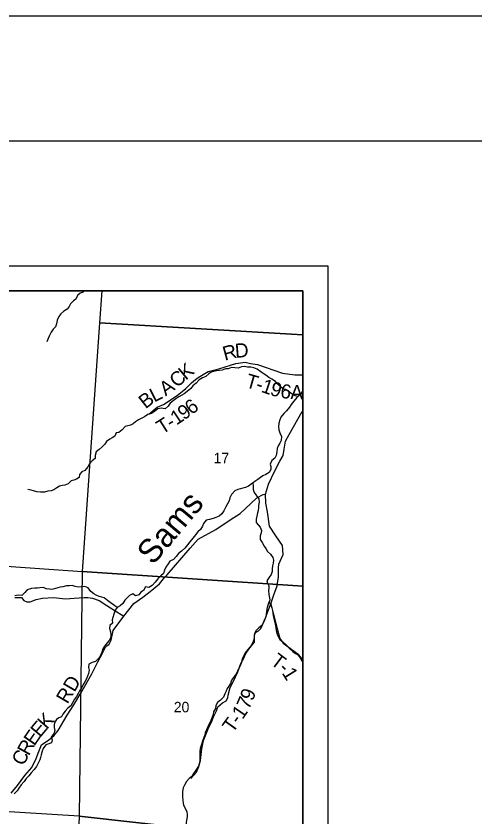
# Model space of a CAD drawing. Extents: x -13.1 to 43.1, y 0 to 22.
# Drawn here: x 7.753 to 9.588, y 18.795 to 22 of the extents above; entities that cross this region are included whole.
import ezdxf

# ---------------------------------------------------------------- set-up
doc = ezdxf.new("R2010")
doc.units = 0
for name, color, linetype in [('GM_X_Corporation', 7, 'Continuous'), ('GM_X_Minor_River', 7, 'Continuous'), ('GM_X_Minor_River_Text', 7, 'Continuous'), ('GM_X_Section_Text', 7, 'Continuous'), ('GM_X_Township_Road', 7, 'Continuous'), ('GM_X_Township_Road_Text', 7, 'Continuous'), ('SH_Border', 7, 'Continuous'), ('SH_Data', 7, 'Continuous')]:
    doc.layers.add(name, color=color, linetype=linetype)

msp = doc.modelspace()

# ---------------------------------------------------------------- linework, layer by layer
at = {"layer": 'GM_X_Corporation'}
for points in [[(8.9, 15.7487), (8.9, 20.9), (7.0804, 20.9), (7.0615, 20.6138), (7.0162, 19.896), (7.0106, 19.8452), (6.9616, 19.1692), (6.9507, 19.0184), (6.8365, 17.1257), (6.8234, 16.908), (6.7528, 15.9566), (7.8612, 15.855), (8.7782, 15.7572)], [(8.9, 15.7487), (8.9, 20.9), (7.0804, 20.9), (7.0615, 20.6138), (7.0162, 19.896), (7.0106, 19.8452), (6.9616, 19.1692), (6.9507, 19.0184), (6.8365, 17.1257), (6.8234, 16.908), (6.7528, 15.9566), (7.8612, 15.855), (8.7782, 15.7572)], [(8.9, 15.7481), (8.9, 20.9), (7.0807, 20.9), (7.0617, 20.6133), (7.0164, 19.8954), (7.0108, 19.8446), (6.9509, 19.0179), (6.8236, 16.9075), (6.7531, 15.956), (7.8614, 15.8545), (8.7784, 15.7567)], [(8.9, 20.7241), (8.9, 20.9), (8.0957, 20.9), (8.0867, 20.7729)], [(8.9, 19.7189), (8.9, 20.7241), (8.0867, 20.7729), (8.018, 19.7768)], [(7.0116, 19.8485), (8.018, 19.7768), (8.0053, 18.7983), (6.947, 18.8637), (6.949, 18.894)], [(8.9, 18.698), (8.9, 19.7189), (8.018, 19.7768), (8.0053, 18.7983)], [(8.9, 17.7183), (8.9, 18.698), (8.0053, 18.7983), (7.9639, 17.8036)]]:
    msp.add_lwpolyline(points, close=True, dxfattribs=at)
at = {"layer": 'GM_X_Minor_River'}
for p, q in [((8.0214, 20.8952), (8.01, 20.8907)), ((8.024, 20.9), (8.0214, 20.8952)), ((7.9921, 20.8674), (7.9825, 20.8598)), ((7.9986, 20.8813), (7.9921, 20.8674)), ((8.01, 20.8907), (7.9986, 20.8813)), ((7.9653, 20.8372), (7.9573, 20.8274)), ((7.9715, 20.8485), (7.9653, 20.8372)), ((7.9825, 20.8598), (7.9715, 20.8485)), ((7.9322, 20.8082), (7.9245, 20.7984)), ((7.9448, 20.8191), (7.9322, 20.8082)), ((7.9573, 20.8274), (7.9448, 20.8191)), ((7.9152, 20.7685), (7.9114, 20.7567)), ((7.9172, 20.7836), (7.9152, 20.7685)), ((7.9245, 20.7984), (7.9172, 20.7836)), ((7.893, 20.7349), (7.8853, 20.7197)), ((7.9022, 20.7466), (7.893, 20.7349)), ((7.9114, 20.7567), (7.9022, 20.7466)), ((7.8811, 20.7099), (7.8757, 20.6967)), ((7.8853, 20.7197), (7.8811, 20.7099)), ((8.5334, 20.5752), (8.5239, 20.5688)), ((8.5444, 20.5782), (8.5334, 20.5752)), ((8.5554, 20.5804), (8.5444, 20.5782)), ((8.5664, 20.5811), (8.5554, 20.5804)), ((8.5774, 20.5833), (8.5664, 20.5811)), ((8.5914, 20.5877), (8.5774, 20.5833)), ((8.602, 20.5881), (8.5914, 20.5877)), ((8.6149, 20.594), (8.602, 20.5881)), ((8.6282, 20.5917), (8.6149, 20.594)), ((8.6414, 20.5905), (8.6282, 20.5917)), ((8.6551, 20.5961), (8.6414, 20.5905)), ((8.6653, 20.5971), (8.6551, 20.5961)), ((8.6786, 20.5955), (8.6653, 20.5971)), ((8.6922, 20.5947), (8.6786, 20.5955)), ((8.7035, 20.5927), (8.6922, 20.5947)), ((8.7168, 20.5869), (8.7035, 20.5927)), ((8.7318, 20.5758), (8.7168, 20.5869)), ((8.742, 20.5697), (8.7318, 20.5758)), ((8.4851, 20.5448), (8.4729, 20.5312)), ((8.4991, 20.5527), (8.4851, 20.5448)), ((8.5121, 20.5579), (8.4991, 20.5527)), ((8.5239, 20.5688), (8.5121, 20.5579)), ((8.7526, 20.5624), (8.742, 20.5697)), ((8.7646, 20.554), (8.7526, 20.5624)), ((8.7763, 20.5467), (8.7646, 20.554)), ((8.7903, 20.5383), (8.7763, 20.5467)), ((8.4607, 20.5199), (8.4519, 20.5098)), ((8.4729, 20.5312), (8.4607, 20.5199)), ((8.8004, 20.5265), (8.7903, 20.5383)), ((8.8102, 20.5158), (8.8004, 20.5265)), ((8.8211, 20.5081), (8.8102, 20.5158)), ((8.4161, 20.4834), (8.4035, 20.4763)), ((8.426, 20.4879), (8.4161, 20.4834)), ((8.4381, 20.4973), (8.426, 20.4879)), ((8.4519, 20.5098), (8.4381, 20.4973)), ((8.8309, 20.505), (8.8211, 20.5081)), ((8.8449, 20.4962), (8.8309, 20.505)), ((8.8588, 20.4851), (8.8449, 20.4962)), ((8.869, 20.4809), (8.8588, 20.4851)), ((8.8809, 20.4772), (8.869, 20.4809)), ((8.3696, 20.4507), (8.3616, 20.4387)), ((8.3811, 20.4605), (8.3696, 20.4507)), ((8.3921, 20.468), (8.3811, 20.4605)), ((8.4035, 20.4763), (8.3921, 20.468)), ((8.3069, 20.4178), (8.2951, 20.4095)), ((8.3199, 20.4279), (8.3069, 20.4178)), ((8.3331, 20.4305), (8.3199, 20.4279)), ((8.3494, 20.4289), (8.3331, 20.4305)), ((8.3616, 20.4387), (8.3494, 20.4289)), ((8.2423, 20.3848), (8.2313, 20.3758)), ((8.256, 20.3908), (8.2423, 20.3848)), ((8.2663, 20.3968), (8.256, 20.3908)), ((8.2799, 20.405), (8.2663, 20.3968)), ((8.2951, 20.4095), (8.2799, 20.405)), ((8.1898, 20.3575), (8.1776, 20.3443)), ((8.2001, 20.3604), (8.1898, 20.3575)), ((8.2103, 20.3623), (8.2001, 20.3604)), ((8.221, 20.3683), (8.2103, 20.3623)), ((8.2313, 20.3758), (8.221, 20.3683)), ((8.1487, 20.3194), (8.1376, 20.3123)), ((8.1537, 20.3319), (8.1487, 20.3194)), ((8.1647, 20.3341), (8.1537, 20.3319)), ((8.1776, 20.3443), (8.1647, 20.3341)), ((8.1079, 20.2867), (8.0976, 20.2758)), ((8.1152, 20.2976), (8.1079, 20.2867)), ((8.1281, 20.3074), (8.1152, 20.2976)), ((8.1376, 20.3123), (8.1281, 20.3074)), ((8.074, 20.2566), (8.0701, 20.2422)), ((8.0858, 20.2656), (8.074, 20.2566)), ((8.0976, 20.2758), (8.0858, 20.2656)), ((8.0693, 20.2297), (8.0582, 20.2199)), ((8.0701, 20.2422), (8.0693, 20.2297)), ((8.0398, 20.1957), (8.0276, 20.1814)), ((8.0468, 20.2086), (8.0398, 20.1957)), ((8.0582, 20.2199), (8.0468, 20.2086)), ((8.0063, 20.1652), (8.0051, 20.1538)), ((8.0166, 20.1758), (8.0063, 20.1652)), ((8.0276, 20.1814), (8.0166, 20.1758)), ((7.961, 20.1283), (7.9481, 20.1235)), ((7.9736, 20.1404), (7.961, 20.1283)), ((7.9842, 20.143), (7.9736, 20.1404)), ((7.9948, 20.1463), (7.9842, 20.143)), ((8.0051, 20.1538), (7.9948, 20.1463)), ((7.8131, 20.1031), (7.8006, 20.1059)), ((7.8233, 20.1008), (7.8131, 20.1031)), ((7.8369, 20.0961), (7.8233, 20.1008)), ((7.8513, 20.0953), (7.8369, 20.0961)), ((7.8668, 20.0952), (7.8513, 20.0953)), ((7.8801, 20.0985), (7.8668, 20.0952)), ((7.8934, 20.1007), (7.8801, 20.0985)), ((7.9036, 20.1041), (7.8934, 20.1007)), ((7.9158, 20.1123), (7.9036, 20.1041)), ((7.9264, 20.1183), (7.9158, 20.1123)), ((7.9382, 20.1217), (7.9264, 20.1183)), ((7.9481, 20.1235), (7.9382, 20.1217)), ((7.8288, 19.7101), (7.8148, 19.709)), ((7.839, 19.7112), (7.8288, 19.7101)), ((7.8489, 19.7126), (7.839, 19.7112)), ((7.8625, 19.7137), (7.8489, 19.7126)), ((7.8735, 19.7087), (7.8625, 19.7137)), ((7.9197, 19.7125), (7.9068, 19.7077)), ((7.93, 19.7151), (7.9197, 19.7125)), ((7.9398, 19.7166), (7.93, 19.7151)), ((7.955, 19.7195), (7.9398, 19.7166)), ((7.9667, 19.7206), (7.955, 19.7195)), ((7.9773, 19.7213), (7.9667, 19.7206)), ((7.9902, 19.7174), (7.9773, 19.7213)), ((8.0015, 19.715), (7.9902, 19.7174)), ((8.0152, 19.7161), (8.0015, 19.715)), ((8.0288, 19.7179), (8.0152, 19.7161)), ((8.0409, 19.7117), (8.0288, 19.7179)), ((8.0518, 19.6976), (8.0409, 19.7117)), ((7.7612, 19.6825), (7.7487, 19.6799)), ((7.7763, 19.6816), (7.7612, 19.6825)), ((7.7882, 19.6933), (7.7763, 19.6816)), ((7.7981, 19.7038), (7.7882, 19.6933)), ((7.8148, 19.709), (7.7981, 19.7038)), ((7.8863, 19.7067), (7.8735, 19.7087)), ((7.8966, 19.7051), (7.8863, 19.7067)), ((7.9068, 19.7077), (7.8966, 19.7051)), ((8.0638, 19.6877), (8.0518, 19.6976)), ((8.074, 19.6827), (8.0638, 19.6877)), ((8.0861, 19.6769), (8.074, 19.6827)), ((8.0959, 19.6746), (8.0861, 19.6769)), ((8.1057, 19.6719), (8.0959, 19.6746)), ((8.1193, 19.6608), (8.1057, 19.6719)), ((8.1291, 19.6531), (8.1193, 19.6608)), ((8.143, 19.6443), (8.1291, 19.6531)), ((8.7642, 19.6544), (8.7717, 19.6437)), ((8.157, 19.634), (8.143, 19.6443)), ((8.7717, 19.6437), (8.7757, 19.6319)), ((8.7757, 19.6319), (8.7783, 19.6216)), ((8.7783, 19.6216), (8.7801, 19.611)), ((8.7801, 19.611), (8.7819, 19.6)), ((8.7819, 19.6), (8.7845, 19.589)), ((8.7845, 19.589), (8.7871, 19.5772)), ((8.7871, 19.5772), (8.7893, 19.5673)), ((8.7893, 19.5673), (8.7918, 19.554)), ((8.7918, 19.554), (8.7936, 19.5415)), ((8.7936, 19.5415), (8.7973, 19.5271)), ((8.7973, 19.5271), (8.8018, 19.5175)), ((8.8018, 19.5175), (8.8081, 19.505)), ((8.8081, 19.505), (8.8217, 19.4947)), ((8.8217, 19.4947), (8.8345, 19.4832)), ((8.8345, 19.4832), (8.8465, 19.4698)), ((8.8465, 19.4698), (8.8597, 19.458)), ((8.8597, 19.458), (8.8702, 19.4496)), ((8.8702, 19.4496), (8.88, 19.4438)), ((8.88, 19.4438), (8.8898, 19.4324)), ((8.8898, 19.4324), (8.8958, 19.4195)), ((8.8958, 19.4195), (8.9, 19.4132))]:
    msp.add_line(p, q, dxfattribs=at)
for points in [[(8.9, 20.5006), (8.8983, 20.4985), (8.8906, 20.4853), (8.8765, 20.4736), (8.8639, 20.4589), (8.854, 20.4453), (8.8471, 20.4348), (8.8341, 20.4204), (8.8234, 20.4091), (8.8119, 20.3944), (8.8081, 20.3842), (8.8042, 20.3709), (8.8026, 20.3562), (8.8036, 20.3448), (8.8085, 20.3318), (8.8144, 20.3174), (8.8132, 20.3022), (8.8082, 20.2909), (8.8013, 20.2807), (8.797, 20.2693), (8.7958, 20.2564), (8.7938, 20.2413), (8.7884, 20.2307), (8.7759, 20.2221), (8.7689, 20.2069), (8.7723, 20.1974), (8.7718, 20.1853), (8.766, 20.1736), (8.7523, 20.1661), (8.7406, 20.1605), (8.7303, 20.1541), (8.7196, 20.1454), (8.7075, 20.1375), (8.6934, 20.1263), (8.6831, 20.1191), (8.6702, 20.1131), (8.6607, 20.1109), (8.6504, 20.1087), (8.6406, 20.1057), (8.6277, 20.0997)], [(8.6997, 20.1313), (8.7009, 20.1198), (8.7012, 20.1061), (8.7056, 20.0932), (8.7124, 20.0836), (8.724, 20.0688), (8.725, 20.0555), (8.7234, 20.0415), (8.7226, 20.0316), (8.7214, 20.0221), (8.719, 20.0119), (8.7159, 19.9987), (8.7132, 19.9869), (8.7131, 19.974), (8.721, 19.9645), (8.7292, 19.9546), (8.7344, 19.942), (8.7332, 19.9318), (8.7297, 19.9197), (8.73, 19.906), (8.7371, 19.8931), (8.7457, 19.879), (8.7517, 19.8695), (8.7584, 19.8581), (8.7701, 19.8462), (8.7802, 19.8336), (8.7832, 19.8222), (8.7808, 19.8113), (8.7789, 19.7999), (8.7776, 19.7885), (8.7768, 19.7768), (8.7737, 19.7654), (8.7641, 19.7518), (8.7557, 19.7397), (8.759, 19.7302), (8.7643, 19.7203), (8.7638, 19.7109), (8.763, 19.701), (8.764, 19.6851), (8.7673, 19.6725), (8.7676, 19.663), (8.7626, 19.6506), (8.7576, 19.6335), (8.7548, 19.6187), (8.7536, 19.6051), (8.752, 19.5949), (8.7458, 19.5824), (8.742, 19.5722), (8.7366, 19.562), (8.7244, 19.5522), (8.7122, 19.5405), (8.7068, 19.5276), (8.7056, 19.5159), (8.704, 19.5038), (8.6994, 19.4909), (8.6909, 19.4777), (8.6806, 19.466), (8.6695, 19.452), (8.6645, 19.4418), (8.6576, 19.4282), (8.6541, 19.4138), (8.6483, 19.3972), (8.6399, 19.3832), (8.636, 19.3726), (8.6264, 19.3586), (8.6153, 19.342), (8.6103, 19.3295), (8.6042, 19.3186), (8.5973, 19.3087), (8.5934, 19.2981), (8.5877, 19.2876), (8.5823, 19.2751), (8.5712, 19.263), (8.559, 19.2532), (8.5525, 19.2415), (8.5509, 19.2294), (8.5429, 19.2165), (8.5416, 19.2059), (8.5374, 19.1946), (8.532, 19.1813), (8.5262, 19.17), (8.5205, 19.1556), (8.5143, 19.1435), (8.5097, 19.1337), (8.5077, 19.1231), (8.5042, 19.1132), (8.4992, 19.0985), (8.4946, 19.0856), (8.4895, 19.0697), (8.4887, 19.0572), (8.4878, 19.0439), (8.4885, 19.0337), (8.4884, 19.0216), (8.4865, 19.0113), (8.483, 18.9985), (8.4726, 18.983), (8.4634, 18.969), (8.4561, 18.9573), (8.4455, 18.9486), (8.4348, 18.9373), (8.4279, 18.9248)], [(8.6277, 20.0997), (8.6151, 20.0862), (8.6081, 20.0718), (8.605, 20.0601), (8.5993, 20.0487), (8.5916, 20.0359), (8.5847, 20.0208), (8.5762, 20.0083), (8.5652, 19.9985), (8.5523, 19.9929), (8.5409, 19.9892), (8.5268, 19.9855), (8.5128, 19.9825), (8.5029, 19.9697), (8.4982, 19.9584), (8.4902, 19.9455), (8.4807, 19.9365), (8.4707, 19.924), (8.4604, 19.9104), (8.4478, 19.8965), (8.439, 19.884), (8.4279, 19.8712), (8.4153, 19.8584), (8.4032, 19.849), (8.3932, 19.8373), (8.3822, 19.8256), (8.3685, 19.8185), (8.3612, 19.8083), (8.3528, 19.7954), (8.3474, 19.783), (8.3428, 19.7701), (8.3328, 19.7595), (8.3199, 19.7486), (8.3099, 19.7347), (8.2981, 19.7211), (8.284, 19.714), (8.2708, 19.7163), (8.2631, 19.702), (8.2521, 19.6944), (8.2441, 19.6843), (8.2311, 19.6798), (8.2202, 19.6878), (8.2073, 19.6818), (8.1981, 19.672), (8.1878, 19.6622), (8.1802, 19.6494), (8.1695, 19.64), (8.157, 19.634), (8.1489, 19.6223), (8.1439, 19.6068), (8.14, 19.5939), (8.1377, 19.5841), (8.1387, 19.5711), (8.1284, 19.5614), (8.1272, 19.55), (8.1313, 19.5355), (8.1319, 19.5257), (8.1326, 19.5135), (8.1261, 19.5018), (8.1169, 19.4916), (8.1066, 19.4784), (8.0986, 19.4656), (8.0958, 19.4546), (8.0908, 19.441), (8.0839, 19.4312), (8.0709, 19.418), (8.058, 19.4131), (8.0447, 19.4071), (8.0435, 19.3927), (8.0461, 19.3832), (8.0426, 19.3696), (8.0383, 19.3586), (8.0329, 19.3458), (8.0279, 19.3356), (8.0222, 19.3257), (8.0157, 19.3133), (8.0069, 19.3004), (8.0015, 19.2898), (7.995, 19.2777), (7.9873, 19.266), (7.9792, 19.2524), (7.9723, 19.24), (7.9609, 19.2309), (7.9495, 19.2181), (7.9407, 19.2064), (7.9345, 19.1966), (7.9239, 19.1917), (7.9144, 19.1853), (7.9086, 19.1751), (7.9055, 19.1653), (7.9062, 19.1532), (7.9088, 19.141), (7.9037, 19.1281), (7.893, 19.1161), (7.8975, 19.1039), (7.8951, 19.0918), (7.8845, 19.0873), (7.872, 19.0836), (7.8616, 19.0689), (7.8578, 19.0586), (7.8531, 19.0439)], [(7.8531, 19.0439), (7.8508, 19.0337), (7.8477, 19.0238), (7.8415, 19.0102), (7.8346, 18.9973), (7.8254, 18.9856), (7.814, 18.9724), (7.8037, 18.9596), (7.7937, 18.9487), (7.785, 18.937), (7.7739, 18.9238), (7.7639, 18.9106), (7.757, 18.9), (7.7456, 18.8875)], [(8.4279, 18.9248), (8.4217, 18.9124), (8.4194, 18.8972), (8.4185, 18.8862), (8.4188, 18.876), (8.4199, 18.8623), (8.4209, 18.8498), (8.4235, 18.8392), (8.4321, 18.8254), (8.4362, 18.8152), (8.4376, 18.8057), (8.4372, 18.7954), (8.4352, 18.7829), (8.434, 18.7716), (8.432, 18.7583)]]:
    msp.add_lwpolyline(points, dxfattribs=at)
at = {"layer": 'GM_X_Township_Road'}
for points in [[(8.471, 20.5455), (8.4815, 20.554), (8.522, 20.5771), (8.564, 20.588), (8.6315, 20.6098), (8.6698, 20.6147), (8.6908, 20.6103)], [(8.6908, 20.6103), (8.7193, 20.6052), (8.8187, 20.571), (8.8677, 20.5637), (8.9, 20.565)], [(8.2842, 20.4074), (8.3178, 20.4354), (8.3432, 20.4451), (8.3977, 20.482), (8.4324, 20.5092), (8.455, 20.5325), (8.471, 20.5455)], [(8.0726, 19.4003), (8.0806, 19.4159), (8.0978, 19.4486), (8.1124, 19.4772), (8.126, 19.4861), (8.1339, 19.5029), (8.142, 19.542), (8.1841, 19.5982), (8.224, 19.6494), (8.2603, 19.6751), (8.2897, 19.6977), (8.3264, 19.728), (8.3484, 19.7542), (8.3573, 19.7647), (8.4499, 19.871), (8.4816, 19.9073), (8.5524, 19.945), (8.6098, 19.9838), (8.6491, 20.0095), (8.6918, 20.0494), (8.7167, 20.0727), (8.7413, 20.0854), (8.7504, 20.087), (8.7626, 20.1266), (8.7881, 20.18), (8.8083, 20.2192), (8.8211, 20.2421), (8.8254, 20.2672), (8.8305, 20.2995), (8.8451, 20.3262), (8.898, 20.417), (8.9, 20.4203)], [(8.7725, 19.6486), (8.7837, 19.6836), (8.7979, 19.7201), (8.8033, 19.7559), (8.8023, 19.7923), (8.8041, 19.8072), (8.8145, 19.8308), (8.8216, 19.846), (8.8187, 19.8817), (8.7922, 19.9195), (8.7669, 19.9588), (8.7593, 20.0161), (8.7518, 20.0506), (8.7504, 20.087)], [(7.7478, 19.6739), (7.7752, 19.6733), (7.7848, 19.6613), (7.7962, 19.6564), (7.8099, 19.6561), (7.8338, 19.6658), (7.8584, 19.6705), (7.9032, 19.6728), (7.9504, 19.6682), (7.986, 19.6711), (8.0252, 19.6733), (8.0386, 19.6734)], [(8.0386, 19.6734), (8.0396, 19.6734), (8.0586, 19.6701), (8.0853, 19.6612), (8.1162, 19.6413), (8.1452, 19.6226), (8.1841, 19.5982)], [(8.7068, 19.5207), (8.707, 19.5246), (8.7107, 19.5334), (8.7228, 19.5403), (8.7322, 19.5491), (8.7483, 19.5834), (8.7595, 19.6177), (8.7725, 19.6486)], [(8.7725, 19.6486), (8.7819, 19.6114), (8.7987, 19.5447), (8.8085, 19.5098), (8.8208, 19.4913), (8.8796, 19.4481), (8.8953, 19.4326), (8.9, 19.4219)], [(8.5392, 19.1849), (8.5441, 19.1991), (8.5549, 19.2204), (8.5605, 19.2353), (8.5794, 19.2521), (8.5934, 19.2602), (8.6001, 19.272), (8.602, 19.2827), (8.6101, 19.3127), (8.6183, 19.3303), (8.6307, 19.3558), (8.6397, 19.3764), (8.6527, 19.4091), (8.6621, 19.4286), (8.6726, 19.4488), (8.6838, 19.4664), (8.7004, 19.487), (8.7064, 19.495), (8.7063, 19.5091), (8.7068, 19.5207)], [(7.733, 18.8911), (7.759, 18.9216), (7.7883, 18.961), (7.8166, 18.9938), (7.833, 19.0293), (7.8442, 19.0571), (7.8547, 19.0841), (7.8838, 19.1041), (7.9042, 19.1194), (7.9219, 19.1416), (7.9571, 19.2023), (7.9849, 19.2439), (8.0176, 19.2996), (8.0559, 19.3674), (8.0726, 19.4003)], [(8.452, 18.9492), (8.4754, 18.9749), (8.4847, 18.997), (8.4914, 19.0209), (8.4956, 19.0677), (8.5026, 19.1012), (8.522, 19.148), (8.5366, 19.1774), (8.5392, 19.1849)]]:
    msp.add_lwpolyline(points, dxfattribs=at)
at = {"layer": 'SH_Border'}
msp.add_lwpolyline([(1.5, 21.5), (33.5, 21.5), (33.5, 0.5), (1.5, 0.5)], close=True, dxfattribs=at)
at = {"layer": 'SH_Data'}
for p, q in [((2, 21), (9, 21)), ((9, 21), (9, 14)), ((2.1, 20.9), (8.9, 20.9)), ((8.9, 20.9), (8.9, 14.1))]:
    msp.add_line(p, q, dxfattribs=at)
msp.add_lwpolyline([(0, 0), (34, 0), (34, 22), (0, 22)], close=True, dxfattribs=at)

# ---------------------------------------------------------------- texts
at = {"layer": 'GM_X_Minor_River_Text'}
msp.add_text('Sams', height=0.0947, rotation=50.0018, dxfattribs=at).set_placement((8.3008, 19.7995))
at = {"layer": 'GM_X_Section_Text'}
for s, p in [('17', (8.5431, 20.2104)), ('20', (8.3839, 19.2141))]:
    msp.add_text(s, height=0.04186, rotation=0, dxfattribs=at).set_placement(p)
at = {"layer": 'GM_X_Township_Road_Text'}
for s, height, rotation, p in [('R', 0.0568, 14.9621, (8.588, 20.6203)), ('D', 0.0568, 4.6094, (8.6305, 20.6319)), ('K', 0.0568, 39.7743, (8.4316, 20.5406)), ('C', 0.0568, 41.101, (8.3967, 20.5102)), ('T', 0.0568, 344.0187, (8.6676, 20.5157)), ('1', 0.0568, 341.1849, (8.7298, 20.4968)), ('A', 0.0568, 35.6361, (8.3514, 20.4774)), ('-', 0.0568, 341.3676, (8.7078, 20.5042)), ('9', 0.0568, 343.6564, (8.7655, 20.4847)), ('6', 0.0568, 351.693, (8.8076, 20.473)), ('A', 0.0568, 359.0691, (8.8502, 20.4673)), ('B', 0.0568, 37.9838, (8.2711, 20.4261)), ('L', 0.0568, 26.935, (8.3055, 20.4532)), ('6', 0.0568, 36.9119, (8.4547, 20.4025)), ('1', 0.0568, 33.9539, (8.3944, 20.361)), ('9', 0.0568, 35.0844, (8.4244, 20.3812)), ('T', 0.0568, 32.2148, (8.3372, 20.3247)), ('-', 0.0568, 32.7187, (8.3737, 20.3476)), ('T', 0.0568, 323.1275, (8.7672, 19.4093)), ('-', 0.0568, 316.2255, (8.7999, 19.385)), ('1', 0.0568, 302.0357, (8.8144, 19.3717)), ('RD', 0.05682, 59.5812, (7.9588, 19.2445)), ('9', 0.0568, 68.7022, (8.6993, 19.2562)), ('7', 0.0568, 66.6654, (8.6846, 19.2221)), ('1', 0.0568, 55.531, (8.6589, 19.1827)), ('K', 0.0568, 49.117, (7.8763, 19.143)), ('T', 0.0568, 54.2984, (8.6198, 19.1281)), ('E', 0.0568, 50.2164, (7.8493, 19.1106)), ('-', 0.0568, 54.4471, (8.6447, 19.1628)), ('E', 0.0568, 55.4826, (7.8261, 19.0767)), ('R', 0.0568, 60.6516, (7.8039, 19.0372)), ('C', 0.0568, 61.525, (7.7818, 18.9963))]:
    msp.add_text(s, height=height, rotation=rotation, dxfattribs=at).set_placement(p)

doc.saveas('drawing.dxf')
